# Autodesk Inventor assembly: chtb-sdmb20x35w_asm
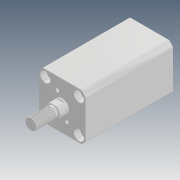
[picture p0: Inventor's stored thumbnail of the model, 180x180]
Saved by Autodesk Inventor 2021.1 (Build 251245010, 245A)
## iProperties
Company: Microsoft
Created: 2018-05
Part Number: chtb-sdmb20x35w_asm
Description: STEP AP214
Document SubType Name: Assembly
Designer: user
Title: chtb-sdmb20x35w_asm.STEP
Author: Windows
Revision Number: ÈÎºÎ
Sending System: SolidWorks 2015
Preprocessor: SwSTEP 2.0
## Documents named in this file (4)
- D:\Vault_2016\Projekty\Clamptek\Hydraulic\CHTB\CHTB-20\Inventor\CHTB-SDMB20x35W\chtb-sdmb20x35w_asm.iam
- D:\Vault_2016\Projekty\Clamptek\Hydraulic\CHTB\CHTB-20\Inventor\CHTB-SDMB20x35W\CHTB-SDMB20X35NBT.ipt
- D:\Vault_2016\Projekty\Clamptek\Hydraulic\CHTB\CHTB-20\Inventor\CHTB-SDMB20x35W\CHTB-SDMB20X35WHSG.ipt
- D:\Vault_2016\Projekty\Clamptek\Hydraulic\CHTB\CHTB-20\Inventor\CHTB-SDMB20x35W\QG_3.ipt
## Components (3 placed, 3 different names)
1. CHTB-SDMB20X35NBT_1
2. CHTB-SDMB20X35WHSG_2
3. QG_3_3
